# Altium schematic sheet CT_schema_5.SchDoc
size 385 x 218 mm
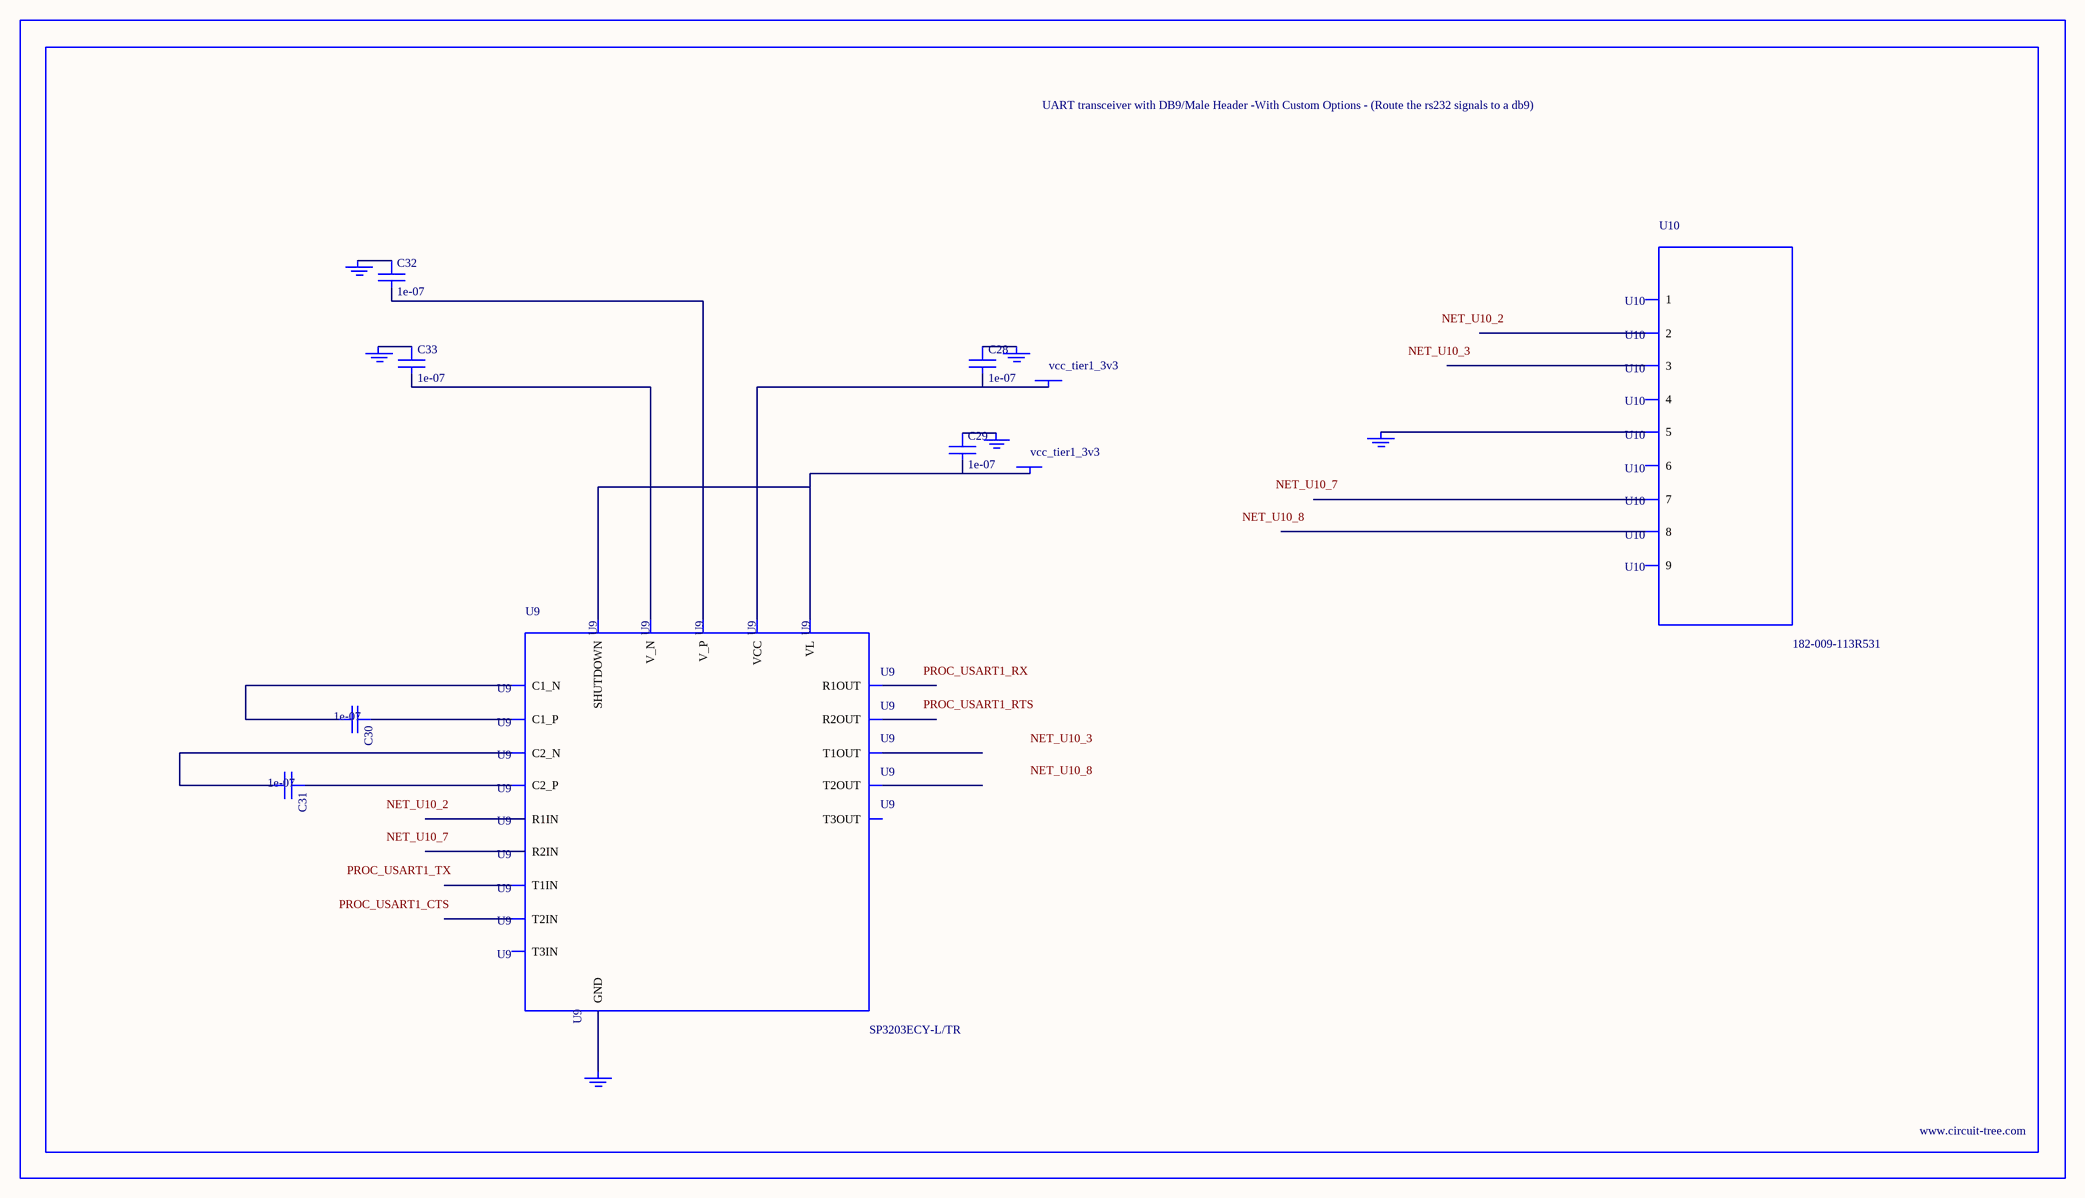
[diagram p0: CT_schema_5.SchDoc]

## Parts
BORDER4  (no value)
C28  1e-07  [C0402]
C29  1e-07  [C0402]
C30  1e-07  [C0402]
C31  1e-07  [C0402]
C32  1e-07  [C0402]
C33  1e-07  [C0402]
GND_INSTANCE_4_0  (no value)
GND_INSTANCE_4_1  (no value)
GND_INSTANCE_4_2  (no value)
GND_INSTANCE_4_3  (no value)
GND_INSTANCE_4_4  (no value)
GND_INSTANCE_4_5  (no value)
POWER_INSTANCE_4_0  vcc_tier1_3v3
POWER_INSTANCE_4_1  vcc_tier1_3v3
U9  SP3203ECY-L/TR  [TSSOP20-I]
U10  182-009-113R531  [182-009-MALE]

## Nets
NetC28_1: C28.1 GND_INSTANCE_4_3.0(GND)
NetC28_2: C28.2 POWER_INSTANCE_4_1.0(PWR) U9.19(VCC)
NetC29_1: C29.1 GND_INSTANCE_4_2.0(GND)
NetC29_2: C29.2 POWER_INSTANCE_4_0.0(PWR) U9.12(VL) U9.20(SHUTDOWN)
NetC30_1: C30.1 U9.1(C1_P)
NetC30_2: C30.2 U9.3(C1_N)
NetC31_1: C31.1 U9.4(C2_P)
NetC31_2: C31.2 U9.5(C2_N)
NetC32_1: C32.1 GND_INSTANCE_4_0.0(GND)
NetC32_2: C32.2 U9.2(V_P)
NetC33_1: C33.1 GND_INSTANCE_4_1.0(GND)
NetC33_2: C33.2 U9.6(V_N)
NetGND_INSTANCE_4_4_0: GND_INSTANCE_4_4.0(GND) U9.18(GND)
NetGND_INSTANCE_4_5_0: GND_INSTANCE_4_5.0(GND) U10.5

Not connected (* = marked no-connect by the designer): U9 7(T1IN) 8(T2IN) 9(T3IN) 10(R2OUT) 11(R1OUT) 13(R2IN) 14(R1IN) 15(T3OUT) 16(T2OUT) 17(T1OUT); U10 1 2 3 4 6 7 8 9

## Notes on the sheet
- Labels drawn without touching a wire or pin: NET_U10_2, NET_U10_3, NET_U10_7, NET_U10_8, PROC_USART1_CTS, PROC_USART1_RTS, PROC_USART1_RX, PROC_USART1_TX

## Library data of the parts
BORDER4 = BORDER_PAGE4
C28-C33 = C0402C104K3RACTU
GND_INSTANCE_4_0-GND_INSTANCE_4_5 = GND
POWER_INSTANCE_4_0 POWER_INSTANCE_4_1 = PWR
